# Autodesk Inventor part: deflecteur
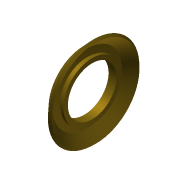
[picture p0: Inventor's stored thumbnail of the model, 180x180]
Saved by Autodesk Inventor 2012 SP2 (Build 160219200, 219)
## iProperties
Created: 2013-04
Part Number: deflecteur
Material: Default
Document SubType Name: Modeling
Designer: papa
Density: 1 g/cm^3
Mass: 0.785301 g
Surface Area: 17.265 cm^2
Volume: 0.785301 cm^3
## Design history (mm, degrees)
node "deflecteur1"
node "deflecteur"
node "Base1"
